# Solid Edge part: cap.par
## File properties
Author: CADCIM
Template: Normal.par
Last saved by: CADCIM
Revision: 11
Application: Solid Edge
Accuracy: 0.99
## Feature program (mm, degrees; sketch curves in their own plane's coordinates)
base feature "unnamed BaseFeature 1"
pattern "unnamed Pattern 1"
pattern "unnamed Pattern 2"
Other named dimensions: "Hole_3": Diameter = 6 mm; CounterBoreDiameter = 8 mm
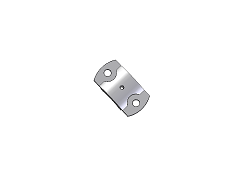
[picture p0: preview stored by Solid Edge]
